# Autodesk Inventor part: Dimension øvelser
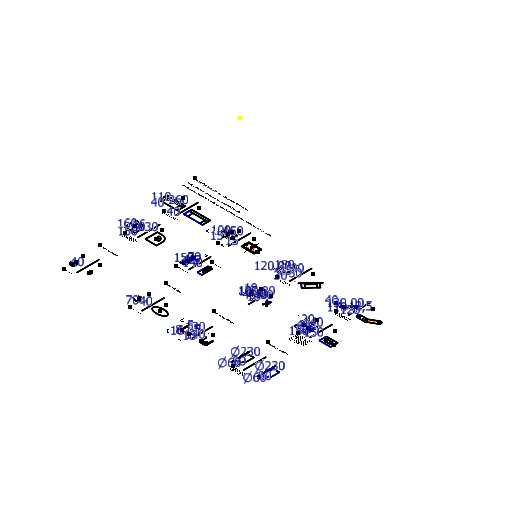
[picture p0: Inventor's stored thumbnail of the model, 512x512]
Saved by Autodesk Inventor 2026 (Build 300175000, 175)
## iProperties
Created: 2013-10
Part Number: Dimension øvelser
Material: Generic
Document SubType Name: Modeling
Designer: Cadskolen
Density: 1 g/cm^3
Appearance: Default
Author: Cadskolen
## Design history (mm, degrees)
sketch "Sketch1" dims "d321" = 40, "d323" = 70
  geometry: L1 (1493.366, -1340.215)-(1493.366, -1656.047); L2 (743.982, -1339.624)-(743.982, -1655.456); L3 (2361.766, -1339.624)-(2361.766, -1655.456); L4 (434.999, -1470.982)-(694.999, -1470.982); L5 (694.999, -1470.982)-(694.999, -1580.982); L6 (694.999, -1580.982)-(434.999, -1580.982); L7 (434.999, -1580.982)-(434.999, -1470.982); L8 (694.999, -1470.982)-(434.999, -1470.982); L9 (434.999, -1470.982)-(434.999, -1505.385); L10 (434.999, -1505.385)-(694.999, -1505.385); L11 (694.999, -1505.385)-(694.999, -1470.982); L12 (694.999, -1505.385)-(654.999, -1505.385); L13 (654.999, -1505.385)-(654.999, -1580.982); L14 (654.999, -1580.982)-(694.999, -1580.982); L15 (694.999, -1580.982)-(694.999, -1505.385); L16 (434.999, -1505.385)-(474.999, -1505.385); L17 (474.999, -1505.385)-(474.999, -1580.982); L18 (474.999, -1580.982)-(434.999, -1580.982); L19 (434.999, -1580.982)-(434.999, -1505.385); L20 (1425.351, -1466.845)-(1425.351, -1566.845); L21 (1275.351, -1566.845)-(1275.351, -1466.845); L22 (1425.351, -1566.845)-(1275.351, -1566.845); L23 (1275.351, -1466.845)-(1425.351, -1466.845); L24 (1410.351, -1551.845)-(1290.351, -1551.845); L25 (1290.351, -1551.845)-(1290.351, -1481.845); L26 (1290.351, -1481.845)-(1410.351, -1481.845); L27 (1410.351, -1481.845)-(1410.351, -1551.845); L28 (1410.351, -1551.845)-(1290.351, -1481.845); L29 (1290.351, -1551.845)-(1410.351, -1481.845); L30 (2097.162, -1625.664)-(2222.505, -1408.564); L31 (2113.886, -1596.697)-(2203.886, -1440.813); L32 (2203.886, -1440.813)-(2281.829, -1485.813); L33 (2281.829, -1485.813)-(2191.829, -1641.697); L34 (2191.829, -1641.697)-(2113.886, -1596.697); L35 (2188.886, -1466.793)-(2203.886, -1440.813); L36 (2203.886, -1440.813)-(2281.829, -1485.813); L37 (2281.829, -1485.813)-(2266.829, -1511.793); L38 (2266.829, -1511.793)-(2188.886, -1466.793); L39 (2113.886, -1596.697)-(2191.829, -1641.697); L40 (2191.829, -1641.697)-(2206.829, -1615.716); L41 (2206.829, -1615.716)-(2128.886, -1570.716); L42 (2128.886, -1570.716)-(2113.886, -1596.697); L43 (2210.537, -1479.293)-(2150.537, -1583.216); L44 (2150.537, -1583.216)-(2128.886, -1570.716); L45 (2128.886, -1570.716)-(2188.886, -1466.793); L46 (2188.886, -1466.793)-(2210.537, -1479.293); L47 (3197.811, -1339.571)-(3197.811, -1655.403); L48 (837.901, -1580.982)-(785.713, -1580.982); L49 (1049.597, -1580.982)-(785.713, -1580.982); L50 (837.901, -1505.385)-(837.901, -1580.982); L51 (785.713, -1505.385)-(837.901, -1505.385); L52 (785.713, -1580.982)-(785.713, -1505.385); L53 (785.713, -1580.982)-(785.713, -1471.434); L54 (785.713, -1471.434)-(785.713, -1505.385); L55 (785.713, -1505.385)-(1049.597, -1505.385); L56 (785.713, -1471.434)-(1049.597, -1471.434); L57 (1049.597, -1471.434)-(785.713, -1471.434); L58 (1049.597, -1471.434)-(1049.597, -1580.982); L59 (1012.229, -1505.385)-(1012.229, -1580.982); L60 (1049.597, -1580.982)-(1049.597, -1505.385); L61 (1012.229, -1580.982)-(1049.597, -1580.982); L62 (1049.597, -1505.385)-(1012.229, -1505.385); L63 (1049.597, -1505.385)-(1049.597, -1471.434); L64 (1604.015, -1478.854)-(1761.64, -1478.854)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; C1 r 12.5 at (3147.114, -1501.893); C2 r 12.5 at (3069.979, -1593.818); C3 r 12.5 at (2959.979, -1593.818); C4 r 5.105 at (3507.567, -1527.196); C5 r 5.105 at (3392.174, -1593.818); C6 r 5.105 at (3287.535, -1593.818); C7 r 1.5 at (2472.244, -2089.705); C8 r 10 at (2241.41, -2085.81); C9 r 12.176 at (1514.696, -2948.009); C10 r 12.176 at (1814.637, -2948.009); A1 r 20 centre (2959.979, -1593.818) between (2959.979, -1573.818) and (2959.979, -1613.818); A2 r 20 centre (3069.979, -1593.818) between (3054.658, -1580.963) and (3085.3, -1606.674); A3 r 20 centre (3147.114, -1501.893) between (3162.434, -1514.749) and (3131.793, -1489.037); A4 r 25 centre (3507.567, -1527.196) between (3520.067, -1548.847) and (3495.067, -1505.546); A5 r 25 centre (3392.174, -1593.818) between (3379.674, -1572.168) and (3404.674, -1615.469); A6 r 25 centre (3287.535, -1593.818) between (3287.535, -1568.818) and (3287.535, -1618.818); A7 r 10 centre (887.612, -2041.7) between (887.612, -2031.7) and (887.612, -2051.7); A8 r 30 centre (887.612, -2081.7) between (917.612, -2081.7) and (887.612, -2051.7); A9 r 40 centre (887.612, -2081.7) between (927.612, -2081.7) and (887.612, -2041.7); A10 r 10 centre (927.612, -2081.7) between (917.612, -2081.7) and (937.612, -2081.7); A11 r 90 centre (887.612, -2081.7) between (977.612, -2081.7) and (887.612, -1991.7); A12 r 50 centre (887.612, -2081.7) between (937.612, -2081.7) and (887.612, -2031.7); A13 r 8 centre (647.42, -2081.7) between (639.42, -2081.7) and (655.42, -2081.7); A14 r 52 centre (587.42, -2081.7) between (639.42, -2081.7) and (587.42, -2029.7); A15 r 60 centre (587.42, -2081.7) between (647.42, -2081.7) and (587.42, -2021.7); A16 r 68 centre (587.42, -2081.7) between (655.42, -2081.7) and (587.42, -2013.7); A17 r 82.761 centre (587.42, -2081.7) between (670.18, -2081.7) and (587.42, -1998.939); A18 r 8 centre (587.42, -2021.7) between (587.42, -2013.7) and (587.42, -2029.7); A19 r 20 centre (1386.028, -2076.609) between (1406.028, -2076.609) and (1366.028, -2076.609); A20 r 20 centre (1386.028, -2176.609) between (1366.028, -2176.609) and (1406.028, -2176.609); A21 r 11.55 centre (1629.743, -2132.782) between (1618.193, -2132.782) and (1641.293, -2132.782); A22 r 11.55 centre (1629.743, -2097.483) between (1641.293, -2097.483) and (1618.193, -2097.483); A23 r 4 centre (2504.812, -2125.731) between (2501.845, -2128.413) and (2507.779, -2123.048); A24 r 4 centre (2439.676, -2053.679) between (2442.643, -2050.997) and (2436.708, -2056.362); A25 r 5 centre (2458.588, -2127.302) between (2453.889, -2125.595) and (2463.288, -2129.009); A26 r 5 centre (2485.9, -2052.108) between (2490.599, -2053.815) and (2481.2, -2050.401); A27 r 10 centre (2170.7, -2015.1) between (2177.771, -2008.029) and (2163.629, -2022.171); A28 r 10 centre (2170.7, -2156.521) between (2163.629, -2149.45) and (2177.771, -2163.592); A29 r 10 centre (2312.121, -2015.1) between (2319.192, -2022.171) and (2305.05, -2008.029); A30 r 10 centre (2312.121, -2156.521) between (2305.05, -2163.592) and (2319.192, -2149.45); A31 r 20 centre (3352.541, -2123.533) between (3352.541, -2103.533) and (3352.541, -2143.533); A32 r 20 centre (3412.541, -2123.533) between (3412.541, -2143.533) and (3412.541, -2103.533); A33 r 40 centre (3068.339, -2098.533) between (3068.339, -2138.533) and (3068.339, -2058.533); A34 r 40 centre (3008.339, -2098.533) between (3008.339, -2058.533) and (3008.339, -2138.533); A35 r 8 centre (2296.724, -3024.746) between (2296.724, -3032.746) and (2304.724, -3024.746); A36 r 8 centre (2202.724, -3024.746) between (2194.724, -3024.746) and (2202.724, -3032.746); A37 r 16 centre (2200.724, -3026.746) between (2184.724, -3026.746) and (2200.724, -3042.746); A38 r 16 centre (2298.724, -3026.746) between (2298.724, -3042.746) and (2314.724, -3026.746); A39 r 10 centre (2477.409, -3022.746) between (2467.409, -3022.746) and (2477.409, -3032.746); A40 r 25 centre (2482.409, -3017.746) between (2457.409, -3017.746) and (2482.409, -3042.746); A41 r 10 centre (2537.409, -3022.746) between (2537.409, -3032.746) and (2547.409, -3022.746); A42 r 25 centre (2532.409, -3017.746) between (2532.409, -3042.746) and (2557.409, -3017.746); 62 further points; 2 other entities
  constraints: 440 end point, 90 point on circle, 88 parallel, 68 tangent, 52 centre point, 44 perpendicular, 26 point on line, 25 midpoint, 23 horizontal, 18 coincident, 10 equal radius, 9 horizontal alignment, 8 collinear, 6 vertical alignment, 1 vertical, 84 other
  dimensions: "d195" = 260 distance of L4.start L4.end; "d196" = 40 distance of L17.end L6.end; "d197" = 40 distance of L13.end L5.end; "d198" = 110 distance between parallel lines of L6 L4; "d199" = 15 distance between parallel lines of L21 L25; "d201" = 100 distance between parallel lines of L22 L23; "d202" = 15 distance between parallel lines of L24 L22; "d204" = 150 distance between parallel lines of L20 L21; "d205" = 30 distance between parallel lines of L34 L41; "d206" = 30 distance between parallel lines of L38 L32; "d208" = 25 distance between parallel lines of L45 L43; "d210" = 180 distance between parallel lines of L34 L32; "d211" = 90 distance of L31.end L32.end; "d219" = 130 deg angle of L96 L95; "d223" = 120 distance of L95.start L95.end; "d224" = 110 distance of L95.end L96.end; "d225" = 40 distance between parallel lines of L91 L94; "d257" = 12.5 radius of C1; "d295" = 60 radius of A15; "d296" = 150 distance between parallel lines of L108 L110; "d297" = 160 distance of L109.end L110.end; "d298" = 16 diameter of A18; "d299" = 130 dimension on A17; "d300" = 70 distance of L117.end L113.start; "d301" = 5 distance from line of L115.end L118; "d302" = 150 distance of L117.start L117.end; "d303" = 140 distance of L115.start L115.end; "d304" = 40 distance between parallel lines of L116 L112; "d305" = 100 distance of point (2241.41, -2085.81) L142.end; "d306" = 10 radius of A29; "d307" = 100 distance of point (2241.41, -2085.81) L141.end; "d308" = 10 radius of A27; "d309" = 10 radius of C8; "d310" = 45 deg angle of L142 L136; "d311" = 135 deg angle of L141 L136; "d312" = 180 distance of L160.end L161.start; "d313" = 150 distance of L156.end L160.end; "d314" = 40 radius of A34; "d319" = 20 distance edge to line of A34 L161; "d320" = 140 dimension on A33 A34; "d322" = 40 distance of L170.start L170.end; "d326" = 10 distance between parallel lines of L185 L186; "d327" = 8 radius of A36; "d328" = 16 radius of A37; "d329" = 140 distance between parallel lines of L184 L185; "d330" = 5 horizontal distance of L181.start L178.end; "d331" = 5 horizontal distance of L181.start L178.end; "d332" = 130 distance between parallel lines of L179 L180; "d333" = 5 horizontal distance of L183.start L177.start; "d334" = 5 horizontal distance of L183.start L177.start; "d356" = 230 diameter of L201 L199; "d358" = 60 diameter of L204 L199; "d360" = 90 distance between parallel lines of L202 L199; "d361" = 230 diameter of L207 L208; "d362" = 60 diameter of L209 L208; "d363" = 90 distance between parallel lines of L211 L208; "d364" = 120 deg angle of L213 L30
